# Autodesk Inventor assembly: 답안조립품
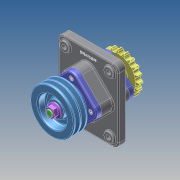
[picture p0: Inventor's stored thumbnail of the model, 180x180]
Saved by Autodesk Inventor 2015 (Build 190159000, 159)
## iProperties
Created: 2026-07
Part Number: 답안조립품
Document SubType Name: Assembly
Designer: user
Author: user
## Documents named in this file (12)
- C:\Users\user\Desktop\760705V1006\답안조립품.iam
- C:\Users\user\Desktop\760705V1006\본체.ipt
- C:\Users\user\Desktop\760705V1006\가져온 구성요소\6각 구멍붙이 볼트 M6x16\6각 구멍붙이 볼트 M6x16.ipt
- C:\Users\user\Desktop\760705V1006\가져온 구성요소\6각 플랜지 너트 M16\6각 플랜지 너트 M16.ipt
- C:\Users\user\Desktop\760705V1006\가져온 구성요소\V-벨트풀리\V-벨트풀리.ipt
- C:\Users\user\Desktop\760705V1006\가져온 구성요소\깊은 홈 볼 베어링 6206\깊은 홈 볼 베어링 6206.ipt
- C:\Users\user\Desktop\760705V1006\가져온 구성요소\오일 실 30 45 8\오일 실 30 45 8.ipt
- C:\Users\user\Desktop\760705V1006\가져온 구성요소\체인 스프로킷\체인 스프로킷.ipt
- C:\Users\user\Desktop\760705V1006\가져온 구성요소\축\축.ipt
- C:\Users\user\Desktop\760705V1006\가져온 구성요소\칼라\칼라.ipt
- C:\Users\user\Desktop\760705V1006\가져온 구성요소\커버\커버.ipt
- C:\Users\user\Desktop\760705V1006\가져온 구성요소\평행 키 6x6x20\평행 키 6x6x20.ipt
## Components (11 placed, 3 different names)
1. 6각 플랜지 너트 M16:1
2. V-벨트풀리:1
3. 6각 플랜지 너트 M16:2
4. 6각 구멍붙이 볼트 M6x16:1
5. 6각 구멍붙이 볼트 M6x16:2
6. 6각 구멍붙이 볼트 M6x16:3
7. 6각 구멍붙이 볼트 M6x16:4
8. 6각 구멍붙이 볼트 M6x16:5
9. 6각 구멍붙이 볼트 M6x16:6
10. 6각 구멍붙이 볼트 M6x16:7
11. 6각 구멍붙이 볼트 M6x16:8
